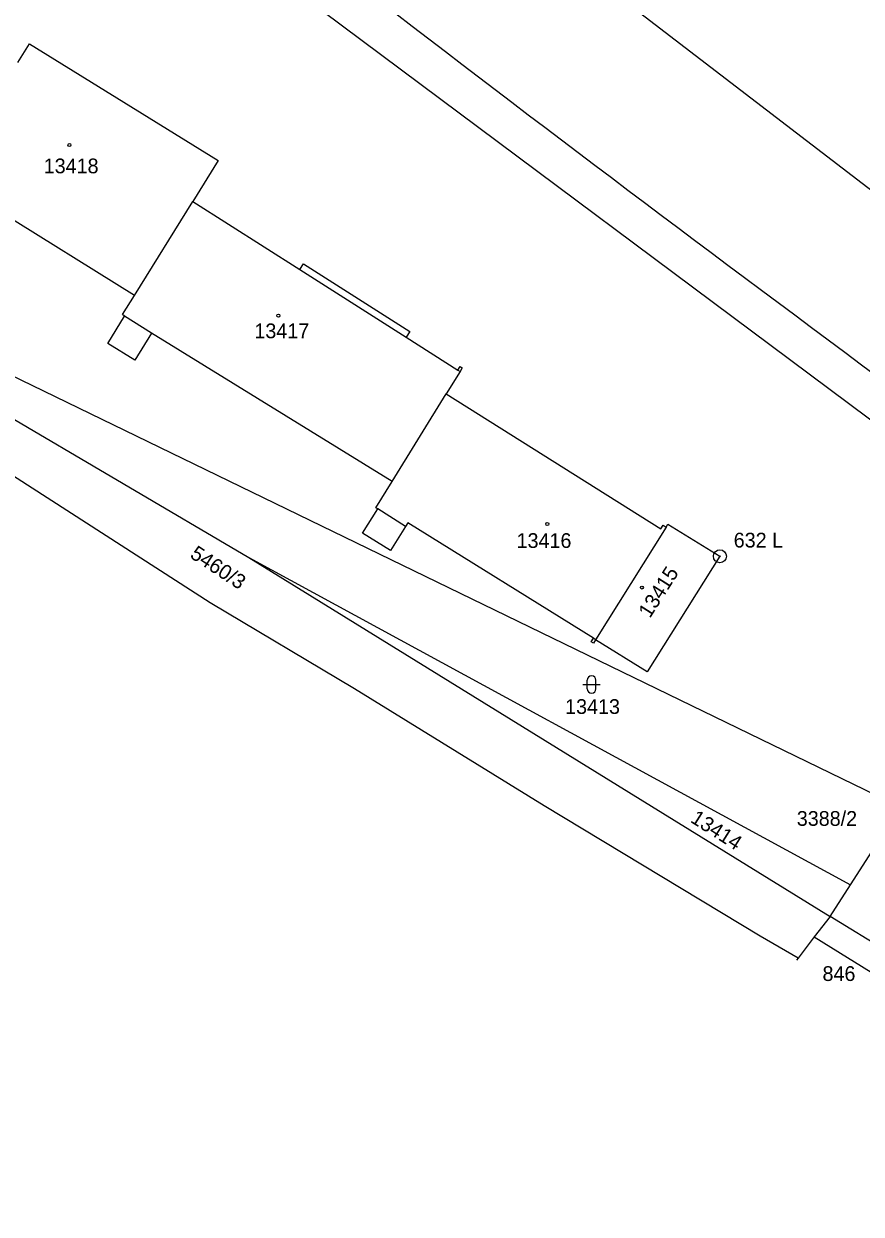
# Model space of a CAD drawing. Extents: x -825057 to -819383, y -1071633 to -1067888.
# Drawn here: x -820419.2 to -820322.7, y -1071624.1 to -1071486.9 of the extents above; entities that cross this region are included whole.
import ezdxf

# ---------------------------------------------------------------- set-up
doc = ezdxf.new("R2010")
doc.units = 0
for name, color, linetype in [('Vrstva 1', 7, 'Continuous'), ('Vrstva 10', 7, 'Continuous'), ('Vrstva 16', 7, 'Continuous'), ('Vrstva 17', 7, 'Continuous'), ('Vrstva 18', 7, 'Continuous'), ('Vrstva 19', 7, 'Continuous'), ('Vrstva 24', 7, 'Continuous'), ('Vrstva 25', 7, 'Continuous'), ('Vrstva 4', 7, 'Continuous')]:
    doc.layers.add(name, color=color, linetype=linetype)

msp = doc.modelspace()

# ---------------------------------------------------------------- linework, layer by layer
at = {"layer": 'Vrstva 1'}
for p, q in [((-820302.35, -1071520.81), (-820411.52, -1071437.02)), ((-820419.85, -1071491.35), (-820418.5, -1071489.18)), ((-820418.5, -1071489.18), (-820396.77, -1071502.65)), ((-820396.77, -1071502.65), (-820399.7, -1071507.37)), ((-820467.89, -1071504.46), (-820318.1, -1071577.17)), ((-820467.89, -1071504.46), (-820393.24, -1071548.42)), ((-820406.42, -1071518.19), (-820428.14, -1071504.69)), ((-820406.42, -1071518.19), (-820399.7, -1071507.37)), ((-820399.7, -1071507.37), (-820387.37, -1071515.21)), ((-820387.37, -1071515.21), (-820386.95, -1071514.54)), ((-820386.95, -1071514.54), (-820374.68, -1071522.34)), ((-820407.81, -1071520.41), (-820406.42, -1071518.19)), ((-820409.5, -1071523.73), (-820407.55, -1071520.57)), ((-820407.55, -1071520.57), (-820407.81, -1071520.41)), ((-820374.68, -1071522.34), (-820375.11, -1071523.01)), ((-820406.36, -1071525.66), (-820409.5, -1071523.73)), ((-820404.44, -1071522.56), (-820406.36, -1071525.66)), ((-820376.72, -1071539.66), (-820404.44, -1071522.56)), ((-820375.11, -1071523.01), (-820369.15, -1071526.81)), ((-820369.15, -1071526.81), (-820368.88, -1071526.39)), ((-820368.88, -1071526.39), (-820368.63, -1071526.55)), ((-820368.89, -1071526.97), (-820370.48, -1071529.54)), ((-820368.63, -1071526.55), (-820368.89, -1071526.97)), ((-820376.72, -1071539.66), (-820370.48, -1071529.54)), ((-820370.48, -1071529.54), (-820345.75, -1071545.1)), ((-820397.68, -1071553.62), (-820429.14, -1071533.38)), ((-820378.58, -1071542.66), (-820376.72, -1071539.66)), ((-820380.13, -1071545.59), (-820378.38, -1071542.79)), ((-820378.38, -1071542.79), (-820378.58, -1071542.66)), ((-820376.89, -1071547.6), (-820380.13, -1071545.59)), ((-820375.16, -1071544.81), (-820376.89, -1071547.6)), ((-820374.9, -1071544.39), (-820375.16, -1071544.81)), ((-820353.5, -1071557.68), (-820374.9, -1071544.39)), ((-820345.14, -1071544.89), (-820353.27, -1071557.88)), ((-820345.75, -1071545.1), (-820345.48, -1071544.67)), ((-820345.48, -1071544.67), (-820345.14, -1071544.89)), ((-820345.14, -1071544.89), (-820344.93, -1071544.55)), ((-820344.93, -1071544.55), (-820338.94, -1071548.26)), ((-820393.24, -1071548.42), (-820326.24, -1071589.78)), ((-820393.24, -1071548.42), (-820323.89, -1071586.13)), ((-820338.94, -1071548.26), (-820347.32, -1071561.58)), ((-820381.05, -1071563.55), (-820397.68, -1071553.62)), ((-820353.77, -1071558.11), (-820353.5, -1071557.68)), ((-820353.27, -1071557.88), (-820353.51, -1071558.27)), ((-820347.32, -1071561.58), (-820353.27, -1071557.88)), ((-820353.51, -1071558.27), (-820353.77, -1071558.11)), ((-820359.19, -1071577.02), (-820381.05, -1071563.55)), ((-820334.29, -1071592.05), (-820359.19, -1071577.02)), ((-820323.89, -1071586.13), (-820321.03, -1071581.71)), ((-820326.24, -1071589.78), (-820323.89, -1071586.13)), ((-820326.24, -1071589.78), (-820328.06, -1071592.14)), ((-820316.2, -1071595.94), (-820326.24, -1071589.78)), ((-820329.93, -1071594.57), (-820334.29, -1071592.05)), ((-820328.06, -1071592.14), (-820329.93, -1071594.57)), ((-820328.06, -1071592.14), (-820276.6, -1071624.09)), ((-820329.93, -1071594.57), (-820330.12, -1071594.82))]:
    msp.add_line(p, q, dxfattribs=at)
at = {"layer": 'Vrstva 10'}
msp.add_line((-820261.7, -1071577.19), (-820384.69, -1071485.49), dxfattribs=at)
msp.add_spline([(-820648.37, -1071145.75), (-820635.21, -1071175.92), (-820619.77, -1071208), (-820606.88, -1071231.72), (-820592.84, -1071254.92), (-820557.31, -1071306.48), (-820522.72, -1071349.67), (-820487.72, -1071388.36), (-820440.04, -1071434.15), (-820382.01, -1071481.32), (-820258.78, -1071573.12)], degree=3, dxfattribs=at)
at = {"layer": 'Vrstva 24'}
for radius in [0.75, 0.0327]:
    msp.add_circle((-820338.94, -1071548.26), radius, dxfattribs=at)
at = {"layer": 'Vrstva 25'}
for p, q in [((-820354.72, -1071563.04), (-820352.72, -1071563.04)), ((-820354.22, -1071563.54), (-820354.22, -1071562.54)), ((-820353.22, -1071563.54), (-820353.22, -1071562.54))]:
    msp.add_line(p, q, dxfattribs=at)
for centre in [(-820413.91, -1071500.86), (-820389.83, -1071520.53), (-820358.83, -1071544.54), (-820347.93, -1071551.87)]:
    msp.add_circle(centre, 0.175, dxfattribs=at)
for centre, start, end in [((-820353.72, -1071562.54), 0, 180), ((-820353.72, -1071563.54), 180, 0)]:
    msp.add_arc(centre, 0.5, start, end, dxfattribs=at)
at = {"layer": 'Vrstva 4'}
for p, q in [((-820387.37, -1071515.21), (-820375.11, -1071523.01)), ((-820404.44, -1071522.56), (-820407.55, -1071520.57)), ((-820369.15, -1071526.81), (-820368.89, -1071526.97)), ((-820375.16, -1071544.81), (-820378.38, -1071542.79)), ((-820353.27, -1071557.88), (-820353.5, -1071557.68))]:
    msp.add_line(p, q, dxfattribs=at)

# ---------------------------------------------------------------- texts
at = {"layer": 'Vrstva 16'}
msp.add_text('3388/2', height=1.7, dxfattribs=at).set_placement((-820330.076, -1071579.33))
at = {"layer": 'Vrstva 17'}
for s, p in [('632 L', (-820337.346, -1071547.25)), ('846', (-820327.108, -1071597.21))]:
    msp.add_text(s, height=1.7, dxfattribs=at).set_placement(p)
at = {"layer": 'Vrstva 18'}
for s, rotation, p in [('5460/3', 326.7, (-820400.129, -1071548.345)), ('13414', 327.6, (-820342.439, -1071578.832))]:
    msp.add_text(s, height=1.7, rotation=rotation, dxfattribs=at).set_placement(p)
msp.add_text('13413', height=1.7, dxfattribs=at).set_placement((-820356.78, -1071566.43))
at = {"layer": 'Vrstva 19'}
for s, p in [('13418', (-820416.88, -1071504.12)), ('13417', (-820392.598, -1071523.13)), ('13416', (-820362.373, -1071547.3))]:
    msp.add_text(s, height=1.7, dxfattribs=at).set_placement(p)
msp.add_text('13415', height=1.7, rotation=57.6, dxfattribs=at).set_placement((-820347.01, -1071555.484))

doc.saveas('drawing.dxf')
